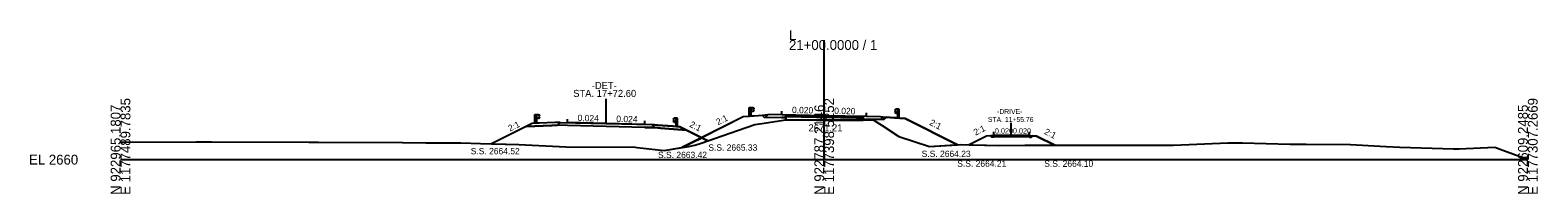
# Model space of a CAD drawing. Extents: x -26 to 1403, y -10 to 9563.
# Drawn here: x 974.3 to 1402.8, y 990.3 to 1036.7 of the extents above; entities that cross this region are included whole.
import ezdxf

# ---------------------------------------------------------------- set-up
doc = ezdxf.new("R2010")
doc.units = 0
for name, color, linetype in [('Exist Cross Section Cell', 7, 'Continuous'), ('Exist XS Center Line Elevation Label', 7, 'Continuous'), ('Exist XS Ground Line', 7, 'Continuous'), ('Prop XS Ditch Slope Text', 7, 'Continuous'), ('Prop XS Dump Level', 7, 'Continuous'), ('Prop XS Earthwork Shape', 7, 'Continuous'), ('Prop XS EOT Tick Mark', 7, 'Continuous'), ('Prop XS Finish Grade', 7, 'Continuous'), ('Prop XS Finish Grade Earthwork', 7, 'Continuous'), ('Prop XS Finish Grade Paved Shoulder', 7, 'Continuous'), ('Prop XS Finish Grade Pavement', 7, 'Continuous'), ('Prop XS Guardrail', 7, 'Continuous'), ('Prop XS Pvmt Edge Slope', 7, 'Continuous'), ('Prop XS SE Text', 7, 'Continuous'), ('Prop XS Shoulder Borrow Shape', 7, 'Continuous'), ('Prop XS Side Slope Text', 7, 'Continuous'), ('Prop XS SS Elevation Text', 7, 'Continuous'), ('Prop XS Subgrade Earthwork', 7, 'Continuous'), ('Prop XS Vertical Lines', 7, 'Continuous'), ('Prop XS Vertical Lines Alignments', 7, 'Continuous'), ('Prop XS Wedging', 7, 'Continuous')]:
    doc.layers.add(name, color=color, linetype=linetype)

msp = doc.modelspace()

# ---------------------------------------------------------------- linework, layer by layer
at = {"layer": 'Exist Cross Section Cell'}
for p, q in [((1200, 1000), (1200, 1033.94)), ((1000, 1000), (1200, 1000)), ((1200, 1000), (1400, 1000))]:
    msp.add_line(p, q, dxfattribs=at)
at = {"layer": 'Exist XS Ground Line'}
for p, q in [((1165.06, 1004.66), (1173.17, 1007.51)), ((1173.17, 1007.51), (1180.25, 1010)), ((1180.25, 1010), (1182.29, 1010.26)), ((1182.29, 1010.26), (1189.14, 1011.26)), ((1189.14, 1011.26), (1197.83, 1011.21)), ((1197.83, 1011.21), (1199.77, 1011.21)), ((1199.77, 1011.21), (1209.17, 1011.23)), ((1209.17, 1011.23), (1211.12, 1011.25)), ((1211.12, 1011.25), (1212.24, 1011.28)), ((1212.24, 1011.28), (1213.89, 1011.31)), ((1213.89, 1011.31), (1216.52, 1009.68)), ((1216.52, 1009.68), (1221.24, 1006.53)), ((1000, 1004.95), (1000.63, 1004.96)), ((1000.63, 1004.96), (1021.52, 1005.06)), ((1021.52, 1005.06), (1024.86, 1005.07)), ((1024.86, 1005.07), (1025.41, 1005.07)), ((1025.41, 1005.07), (1025.81, 1005.07)), ((1025.81, 1005.07), (1053.51, 1004.96)), ((1053.51, 1004.96), (1056.24, 1004.97)), ((1056.24, 1004.97), (1080.14, 1004.89)), ((1080.14, 1004.89), (1086.78, 1004.78)), ((1086.78, 1004.78), (1096.75, 1004.74)), ((1096.75, 1004.74), (1102.35, 1004.6)), ((1102.35, 1004.6), (1113.21, 1004.33)), ((1113.21, 1004.33), (1126.53, 1003.59)), ((1126.53, 1003.59), (1146.24, 1003.52)), ((1146.24, 1003.52), (1146.85, 1003.47)), ((1146.85, 1003.47), (1154.52, 1002.55)), ((1154.52, 1002.55), (1161.41, 1003.74)), ((1161.41, 1003.74), (1163.19, 1004.08)), ((1163.19, 1004.08), (1165.06, 1004.66)), ((1221.24, 1006.53), (1229.92, 1003.76)), ((1229.92, 1003.76), (1238.6, 1004.28)), ((1238.6, 1004.28), (1249.85, 1003.97)), ((1249.85, 1003.97), (1256.99, 1004.09)), ((1256.99, 1004.09), (1276.34, 1004.12)), ((1276.34, 1004.12), (1278.03, 1004.12)), ((1278.03, 1004.12), (1279.28, 1004.14)), ((1279.28, 1004.14), (1299.29, 1004.1)), ((1299.29, 1004.1), (1314.73, 1004.77)), ((1314.73, 1004.77), (1315.96, 1004.81)), ((1315.96, 1004.81), (1318.9, 1004.74)), ((1318.9, 1004.74), (1332.37, 1004.35)), ((1332.37, 1004.35), (1336.96, 1004.41)), ((1336.96, 1004.41), (1349.63, 1004.32)), ((1349.63, 1004.32), (1359.75, 1003.73)), ((1359.75, 1003.73), (1363.62, 1003.54)), ((1363.62, 1003.54), (1378.83, 1003.06)), ((1378.83, 1003.06), (1379.22, 1003.04)), ((1379.22, 1003.04), (1380.45, 1003.1)), ((1380.45, 1003.1), (1390.6, 1003.56)), ((1390.6, 1003.56), (1392.88, 1002.71)), ((1392.88, 1002.71), (1398.54, 1000.6)), ((1398.54, 1000.6), (1400, 1000.6))]:
    msp.add_line(p, q, dxfattribs=at)
at = {"layer": 'Prop XS Dump Level'}
for p, q in [((1188, 1012.78), (1200, 1012.54)), ((1200, 1012.54), (1212, 1012.3)), ((1125, 1010.57), (1138, 1010.26)), ((1138, 1010.26), (1127, 1010.52)), ((1149, 1010), (1138, 1010.26)), ((1138, 1010.26), (1151, 1009.96)), ((1248.17, 1006.85), (1253.17, 1006.95)), ((1253.17, 1006.95), (1248.17, 1006.85)), ((1253.17, 1006.95), (1258.36, 1006.85)), ((1258.36, 1006.85), (1253.17, 1006.95))]:
    msp.add_line(p, q, dxfattribs=at)
at = {"layer": 'Prop XS Earthwork Shape'}
for p, q in [((1177, 1012.14), (1165.18, 1006.23)), ((1178.68, 1012.27), (1177, 1012.14)), ((1182.43, 1012.57), (1180, 1012.38)), ((1183.15, 1011.85), (1182.43, 1012.57)), ((1188, 1011.94), (1183.15, 1011.85)), ((1189.14, 1011.92), (1188, 1011.94)), ((1189.14, 1011.26), (1189.14, 1011.92)), ((1216.85, 1011.37), (1211.12, 1011.48)), ((1211.12, 1011.48), (1211.12, 1011.25)), ((1217.57, 1012.09), (1216.85, 1011.37)), ((1220, 1011.9), (1217.57, 1012.09)), ((1220.82, 1011.83), (1220, 1011.9)), ((1237.85, 1004.23), (1223, 1011.66)), ((1115.31, 1009.44), (1105.48, 1004.52)), ((1122.62, 1009.7), (1115.31, 1009.44)), ((1124.19, 1009.76), (1122.62, 1009.7)), ((1127, 1009.69), (1124.19, 1009.76)), ((1138, 1009.43), (1127, 1009.69)), ((1149, 1009.17), (1138, 1009.43)), ((1151.85, 1009.1), (1149, 1009.17)), ((1153.43, 1008.98), (1151.85, 1009.1)), ((1160.88, 1008.38), (1153.43, 1008.98)), ((1165.18, 1006.23), (1160.88, 1008.38)), ((1166.97, 1005.33), (1173.17, 1007.51)), ((1173.17, 1007.51), (1180.25, 1010)), ((1180.25, 1010), (1182.29, 1010.26)), ((1182.29, 1010.26), (1189.14, 1011.26)), ((1211.12, 1011.25), (1212.24, 1011.28)), ((1212.24, 1011.28), (1213.89, 1011.31)), ((1213.89, 1011.31), (1216.52, 1009.68)), ((1216.52, 1009.68), (1221.24, 1006.53)), ((1105.48, 1004.52), (1113.21, 1004.33)), ((1113.21, 1004.33), (1126.53, 1003.59)), ((1126.53, 1003.59), (1146.24, 1003.52)), ((1146.24, 1003.52), (1146.85, 1003.47)), ((1146.85, 1003.47), (1154.52, 1002.55)), ((1154.52, 1002.55), (1159.57, 1003.42)), ((1159.57, 1003.42), (1165.18, 1006.23)), ((1165.18, 1006.23), (1159.57, 1003.42)), ((1165.18, 1006.23), (1159.57, 1003.42)), ((1159.57, 1003.42), (1161.41, 1003.74)), ((1159.57, 1003.42), (1161.41, 1003.74)), ((1161.41, 1003.74), (1163.19, 1004.08)), ((1161.41, 1003.74), (1163.19, 1004.08)), ((1163.19, 1004.08), (1165.06, 1004.66)), ((1163.19, 1004.08), (1165.06, 1004.66)), ((1165.06, 1004.66), (1166.97, 1005.33)), ((1165.06, 1004.66), (1166.97, 1005.33)), ((1166.97, 1005.33), (1165.18, 1006.23)), ((1166.97, 1005.33), (1165.18, 1006.23)), ((1165.18, 1006.23), (1166.97, 1005.33)), ((1221.24, 1006.53), (1229.92, 1003.76)), ((1229.92, 1003.76), (1237.85, 1004.23))]:
    msp.add_line(p, q, dxfattribs=at)
for points in [[(1180, 1012.38), (1179.18, 1012.31), (1178.68, 1012.27)], [(1223, 1011.66), (1221.32, 1011.79), (1220.82, 1011.83)]]:
    msp.add_lwpolyline(points, dxfattribs=at)
msp.add_lwpolyline([(1246.17, 1006.69), (1241.2, 1004.21), (1249.85, 1003.97), (1256.99, 1004.09), (1265.54, 1004.1), (1260.36, 1006.69), (1259.3, 1006.77), (1258.87, 1006.34), (1258.36, 1006.35), (1253.17, 1006.45), (1248.17, 1006.35), (1247.66, 1006.34), (1247.22, 1006.78)], close=True, dxfattribs=at)
at = {"layer": 'Prop XS EOT Tick Mark'}
for p, q in [((1127, 1010.52), (1127, 1011.52)), ((1188, 1012.78), (1188, 1013.78)), ((1212, 1012.3), (1212, 1013.3)), ((1149, 1010), (1149, 1011)), ((1248.17, 1006.85), (1248.17, 1007.85)), ((1258.36, 1006.85), (1258.36, 1007.85))]:
    msp.add_line(p, q, dxfattribs=at)
at = {"layer": 'Prop XS Finish Grade'}
for p, q in [((1184, 1012.7), (1182.43, 1012.57)), ((1216, 1012.22), (1217.57, 1012.09)), ((1125, 1010.57), (1123.43, 1010.51)), ((1151, 1009.96), (1152.58, 1009.83)), ((1248.17, 1006.85), (1247.22, 1006.78)), ((1258.36, 1006.85), (1259.3, 1006.77))]:
    msp.add_line(p, q, dxfattribs=at)
at = {"layer": 'Prop XS Finish Grade Earthwork'}
for p, q in [((1177, 1012.14), (1159.57, 1003.42)), ((1180, 1012.38), (1177, 1012.14)), ((1182.43, 1012.57), (1180, 1012.38)), ((1217.57, 1012.09), (1220, 1011.9)), ((1220, 1011.9), (1223, 1011.66)), ((1223, 1011.66), (1237.85, 1004.23)), ((1115.31, 1009.44), (1105.48, 1004.52)), ((1117, 1010.28), (1115.31, 1009.44)), ((1119, 1010.35), (1117, 1010.28)), ((1123.43, 1010.51), (1119, 1010.35)), ((1152.58, 1009.83), (1157.01, 1009.48)), ((1157.01, 1009.48), (1159.01, 1009.32)), ((1159.01, 1009.32), (1160.88, 1008.38)), ((1160.88, 1008.38), (1166.97, 1005.33)), ((1246.17, 1006.69), (1241.2, 1004.21)), ((1247.22, 1006.78), (1246.17, 1006.69)), ((1259.3, 1006.77), (1260.36, 1006.69)), ((1260.36, 1006.69), (1265.54, 1004.1))]:
    msp.add_line(p, q, dxfattribs=at)
at = {"layer": 'Prop XS Finish Grade Paved Shoulder'}
for p, q in [((1188, 1012.78), (1184, 1012.7)), ((1212, 1012.3), (1216, 1012.22))]:
    msp.add_line(p, q, dxfattribs=at)
at = {"layer": 'Prop XS Finish Grade Pavement'}
for p, q in [((1188, 1012.78), (1200, 1012.54)), ((1200, 1012.54), (1212, 1012.3)), ((1125, 1010.57), (1138, 1010.26)), ((1138, 1010.26), (1151, 1009.96)), ((1248.17, 1006.85), (1253.17, 1006.95)), ((1253.17, 1006.95), (1258.36, 1006.85))]:
    msp.add_line(p, q, dxfattribs=at)
at = {"layer": 'Prop XS Guardrail'}
for p, q in [((1117.76, 1012.81), (1118.26, 1012.81)), ((1117.76, 1010.31), (1117.76, 1012.81)), ((1118.26, 1012.81), (1118.76, 1012.81)), ((1118.26, 1012.81), (1118.26, 1010.31)), ((1118.76, 1011.68), (1118.26, 1011.68)), ((1118.76, 1012.81), (1119.05, 1012.61)), ((1119.05, 1012.49), (1118.76, 1012.29)), ((1118.76, 1012.29), (1118.76, 1012.2)), ((1118.76, 1012.2), (1119.05, 1012)), ((1119.05, 1011.88), (1118.76, 1011.68)), ((1119.05, 1012.61), (1119.08, 1012.55)), ((1119.08, 1012.55), (1119.05, 1012.49)), ((1119.05, 1012), (1119.08, 1011.94)), ((1119.08, 1011.94), (1119.05, 1011.88)), ((1157.03, 1011.56), (1157, 1011.5)), ((1157, 1011.5), (1157.03, 1011.44)), ((1157.32, 1011.76), (1157.03, 1011.56)), ((1157.03, 1011.44), (1157.32, 1011.24)), ((1157.82, 1011.76), (1157.32, 1011.76)), ((1158.32, 1011.76), (1157.82, 1011.76)), ((1157.82, 1011.76), (1157.82, 1009.26)), ((1158.32, 1009.26), (1158.32, 1011.76)), ((1178.68, 1014.77), (1179.18, 1014.77)), ((1178.68, 1012.27), (1178.68, 1014.77)), ((1179.18, 1014.77), (1179.68, 1014.77)), ((1179.18, 1014.77), (1179.18, 1012.27)), ((1179.68, 1013.64), (1179.18, 1013.64)), ((1179.68, 1014.77), (1179.97, 1014.57)), ((1179.97, 1014.45), (1179.68, 1014.25)), ((1179.68, 1014.25), (1179.68, 1014.16)), ((1179.68, 1014.16), (1179.97, 1013.96)), ((1179.97, 1013.84), (1179.68, 1013.64)), ((1179.97, 1014.57), (1180, 1014.51)), ((1180, 1014.51), (1179.97, 1014.45)), ((1179.97, 1013.96), (1180, 1013.9)), ((1180, 1013.9), (1179.97, 1013.84)), ((1220.03, 1014.09), (1220, 1014.03)), ((1220, 1014.03), (1220.03, 1013.97)), ((1220.03, 1013.48), (1220, 1013.42)), ((1220, 1013.42), (1220.03, 1013.36)), ((1220.32, 1014.29), (1220.03, 1014.09)), ((1220.03, 1013.97), (1220.32, 1013.77)), ((1220.32, 1013.68), (1220.03, 1013.48)), ((1220.03, 1013.36), (1220.32, 1013.16)), ((1220.82, 1014.29), (1220.32, 1014.29)), ((1220.32, 1013.77), (1220.32, 1013.68)), ((1220.32, 1013.16), (1220.82, 1013.16)), ((1221.32, 1014.29), (1220.82, 1014.29)), ((1220.82, 1014.29), (1220.82, 1011.79)), ((1221.32, 1011.79), (1221.32, 1014.29)), ((1157.03, 1010.94), (1157, 1010.88)), ((1157, 1010.88), (1157.03, 1010.82)), ((1157.32, 1011.14), (1157.03, 1010.94)), ((1157.03, 1010.82), (1157.32, 1010.62)), ((1157.32, 1011.24), (1157.32, 1011.14)), ((1157.32, 1010.62), (1157.82, 1010.62))]:
    msp.add_line(p, q, dxfattribs=at)
at = {"layer": 'Prop XS Pvmt Edge Slope'}
for p, q in [((1184, 1012.7), (1183.15, 1011.85)), ((1216, 1012.22), (1216.85, 1011.37)), ((1125, 1010.57), (1124.19, 1009.76)), ((1151, 1009.96), (1151.85, 1009.1)), ((1248.17, 1006.85), (1247.66, 1006.34)), ((1258.36, 1006.85), (1258.87, 1006.34))]:
    msp.add_line(p, q, dxfattribs=at)
at = {"layer": 'Prop XS Shoulder Borrow Shape'}
for p, q in [((1117, 1010.28), (1115.31, 1009.44)), ((1115.31, 1009.44), (1122.62, 1009.7)), ((1117.76, 1010.31), (1117, 1010.28)), ((1123.43, 1010.51), (1119, 1010.35)), ((1122.62, 1009.7), (1124.19, 1009.76)), ((1125, 1010.57), (1123.43, 1010.51)), ((1124.19, 1009.76), (1125, 1010.57)), ((1152.58, 1009.83), (1151, 1009.96)), ((1151, 1009.96), (1151.85, 1009.1)), ((1151.85, 1009.1), (1153.43, 1008.98)), ((1157.01, 1009.48), (1152.58, 1009.83)), ((1153.43, 1008.98), (1160.88, 1008.38)), ((1157.82, 1009.41), (1157.01, 1009.48)), ((1160.88, 1008.38), (1159.01, 1009.32))]:
    msp.add_line(p, q, dxfattribs=at)
for points in [[(1119, 1010.35), (1118.26, 1010.33), (1117.76, 1010.31)], [(1159.01, 1009.32), (1158.32, 1009.37), (1157.82, 1009.41)]]:
    msp.add_lwpolyline(points, dxfattribs=at)
at = {"layer": 'Prop XS Subgrade Earthwork'}
for p, q in [((1183.15, 1011.85), (1182.43, 1012.57)), ((1188, 1011.94), (1183.15, 1011.85)), ((1188, 1011.94), (1189.14, 1011.92)), ((1189.14, 1011.92), (1189.14, 1011.26)), ((1211.12, 1011.48), (1211.12, 1011.25)), ((1211.12, 1011.48), (1216.85, 1011.37)), ((1216.85, 1011.37), (1217.57, 1012.09)), ((1122.62, 1009.7), (1115.31, 1009.44)), ((1124.19, 1009.76), (1122.62, 1009.7)), ((1127, 1009.69), (1124.19, 1009.76)), ((1138, 1009.43), (1127, 1009.69)), ((1149, 1009.17), (1138, 1009.43)), ((1149, 1009.17), (1151.85, 1009.1)), ((1151.85, 1009.1), (1153.43, 1008.98)), ((1153.43, 1008.98), (1160.88, 1008.38)), ((1247.66, 1006.34), (1247.22, 1006.78)), ((1248.17, 1006.35), (1247.66, 1006.34)), ((1253.17, 1006.45), (1248.17, 1006.35)), ((1258.36, 1006.35), (1253.17, 1006.45)), ((1258.36, 1006.35), (1258.87, 1006.34)), ((1258.87, 1006.34), (1259.3, 1006.77))]:
    msp.add_line(p, q, dxfattribs=at)
at = {"layer": 'Prop XS Vertical Lines'}
for p, q in [((1138, 1010.26), (1138, 1017.26)), ((1253.17, 1006.95), (1253.17, 1010.45))]:
    msp.add_line(p, q, dxfattribs=at)
at = {"layer": 'Prop XS Wedging'}
for points in [[(1189.14, 1011.26), (1189.14, 1012.5), (1197.83, 1012.33), (1199.77, 1012.29), (1200, 1012.28), (1209.17, 1012.1), (1211.12, 1012.06), (1211.12, 1011.25), (1209.17, 1011.23), (1200, 1011.21), (1199.77, 1011.21), (1197.83, 1011.21)], [(1189.14, 1011.26), (1189.14, 1012.5), (1197.83, 1012.33), (1199.77, 1012.29), (1200, 1012.28), (1209.17, 1012.1), (1211.12, 1012.06), (1211.12, 1011.25), (1209.17, 1011.23), (1200, 1011.21), (1199.77, 1011.21), (1197.83, 1011.21)], [(1189.14, 1011.26), (1189.14, 1012.25), (1197.83, 1012.08), (1199.77, 1012.04), (1200, 1012.03), (1209.17, 1011.85), (1211.12, 1011.81), (1211.12, 1011.25), (1209.17, 1011.23), (1200, 1011.21), (1199.77, 1011.21), (1197.83, 1011.21)]]:
    msp.add_lwpolyline(points, close=True, dxfattribs=at)

# ---------------------------------------------------------------- texts
at = {"layer": 'Exist Cross Section Cell'}
for s, p in [('21+00.0000 / 1', (1190, 1031.14)), ('L', (1190, 1033.94)), ('EL 2660', (974, 998.6))]:
    msp.add_text(s, height=2.8, dxfattribs=at).set_placement(p)
for s, p in [('E 1177489.7835', (1002.8, 990)), ('E 1177398.5252', (1202.8, 990)), ('E 1177307.2669', (1402.8, 990)), ('N 922965.1807', (1000, 990)), ('N 922787.2146', (1200, 990)), ('N 922609.2485', (1400, 990))]:
    msp.add_text(s, height=2.8, rotation=90, dxfattribs=at).set_placement(p)
at = {"layer": 'Exist XS Center Line Elevation Label'}
msp.add_text('2671.21', height=2, dxfattribs=at).set_placement((1195.53, 1008.02))
at = {"layer": 'Prop XS Ditch Slope Text'}
msp.add_text('2:1', height=1.8, rotation=333.6458, dxfattribs=at).set_placement((1161.55, 1009.43))
at = {"layer": 'Prop XS Dump Level'}
for s, p in [('Case2', (1180, 1012.34)), ('Case2', (1220, 1011.86)), ('Case1', (1119, 1010.19)), ('Case1', (1157, 1009.32)), ('Case1', (1246.17, 1006.65)), ('Case1', (1260.36, 1006.65))]:
    msp.add_text(s, height=0.04, dxfattribs=at).set_placement(p)
at = {"layer": 'Prop XS SE Text'}
for s, height, rotation, p in [('0.024', 1.8, 358.6424, (1129.9, 1010.96)), ('0.024', 1.8, 358.6424, (1140.9, 1010.69)), ('0.020', 1.8, 358.8542, (1190.84, 1013.22)), ('0.020', 1.8, 358.8542, (1202.84, 1012.98)), ('0.020', 1.5, 1.1458, (1248.52, 1007.36)), ('0.020', 1.5, 358.8542, (1253.61, 1007.45))]:
    msp.add_text(s, height=height, rotation=rotation, dxfattribs=at).set_placement(p)
at = {"layer": 'Prop XS Side Slope Text'}
for rotation, p in [(26.5651, (1169.82, 1009.73)), (333.4349, (1229.77, 1009.95)), (26.5651, (1110.7, 1007.93)), (26.5651, (1243.01, 1006.79)), (333.4349, (1262.38, 1007.36))]:
    msp.add_text('2:1', height=1.8, rotation=rotation, dxfattribs=at).set_placement(p)
at = {"layer": 'Prop XS SS Elevation Text'}
for s, p in [('S.S. 2664.52', (1099.54, 1001.52)), ('S.S. 2665.33', (1167.07, 1002.53)), ('S.S. 2663.42', (1152.77, 1000.44)), ('S.S. 2664.23', (1227.71, 1000.76)), ('S.S. 2664.21', (1237.83, 997.97)), ('S.S. 2664.10', (1262.55, 997.96))]:
    msp.add_text(s, height=1.8, dxfattribs=at).set_placement(p)
at = {"layer": 'Prop XS Vertical Lines'}
for s, p in [('-DET-', (1133.93, 1020.05)), ('STA. 17+72.60', (1128.65, 1017.8))]:
    msp.add_text(s, height=2, dxfattribs=at).set_placement(p)
at = {"layer": 'Prop XS Vertical Lines Alignments'}
for s, p in [('STA. 11+55.76', (1246.54, 1010.7)), ('-DRIVE-', (1249.14, 1012.95))]:
    msp.add_text(s, height=1.4, dxfattribs=at).set_placement(p)

doc.saveas('drawing.dxf')
